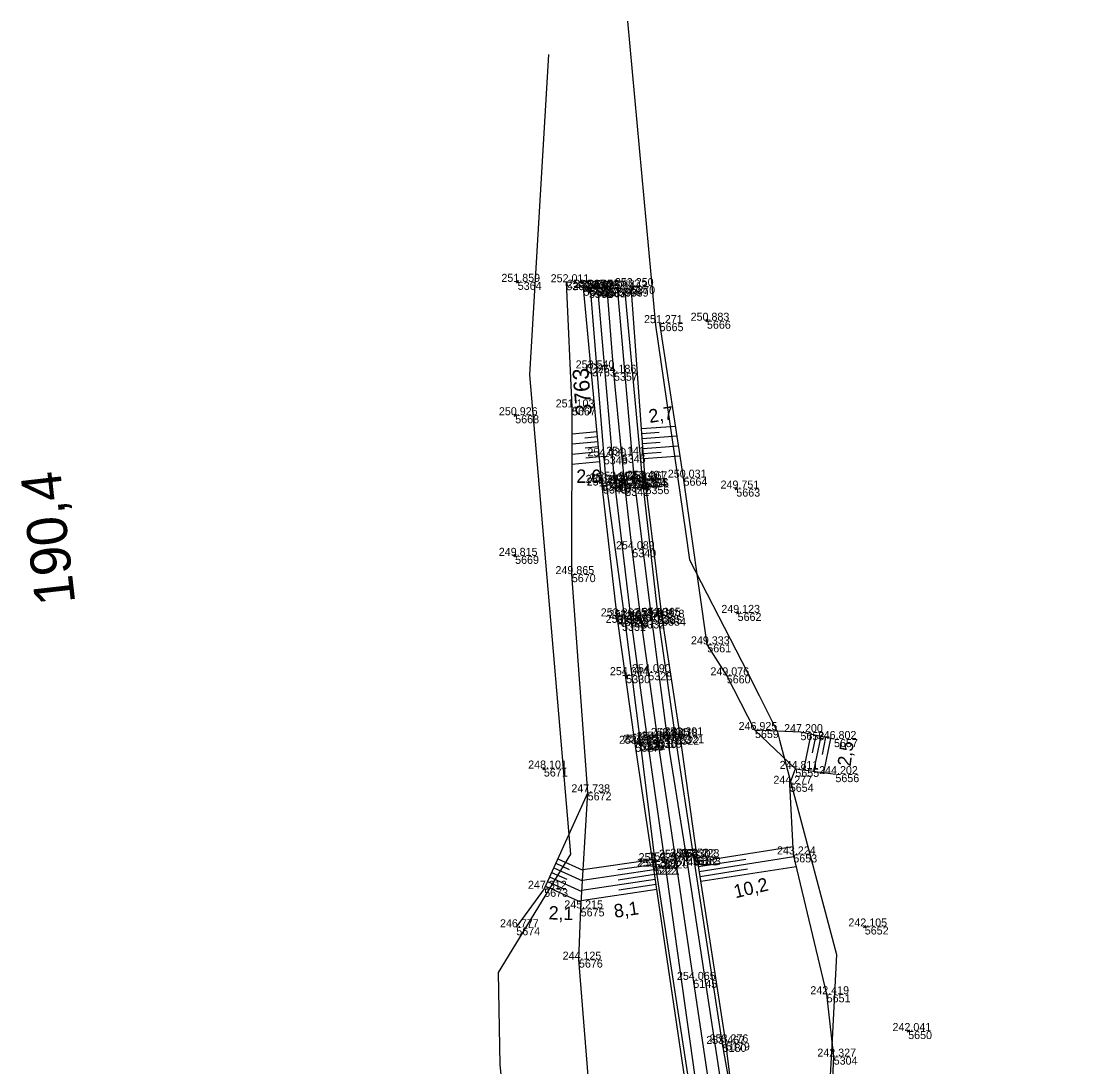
# Model space of a CAD drawing. Extents: x -809970 to -809480, y -1011362 to -1010672.
# Drawn here: x -809970 to -809810.9, y -1010828.7 to -1010672 of the extents above; entities that cross this region are included whole.
import ezdxf

# ---------------------------------------------------------------- set-up
doc = ezdxf.new("R2010")
doc.units = 0
for name, color, linetype in [('Vrstva 1', 7, 'Continuous'), ('Vrstva 4', 7, 'Continuous'), ('Vrstva 48', 7, 'Continuous'), ('Vrstva 49', 7, 'Continuous'), ('Vrstva 53', 7, 'Continuous'), ('Vrstva 60', 7, 'Continuous'), ('Vrstva 61', 7, 'Continuous'), ('Vrstva 63', 7, 'Continuous'), ('Vrstva 7', 7, 'Continuous')]:
    doc.layers.add(name, color=color, linetype=linetype)

msp = doc.modelspace()

# ---------------------------------------------------------------- linework, layer by layer
at = {"layer": 'Vrstva 1'}
msp.add_lwpolyline([(-809865.82, -1010838.83), (-809869.27, -1010815.69), (-809871.97, -1010797.4), (-809874.59, -1010779.68), (-809876.02, -1010769.59), (-809877.07, -1010761.83), (-809878.42, -1010751.16), (-809879.47, -1010741.97), (-809879.54, -1010741.3), (-809879.99, -1010737.01), (-809881.17, -1010724.71), (-809882.19, -1010712.11)], dxfattribs=at)
at = {"layer": 'Vrstva 4'}
for points in [[(-809867.76, -1010839.12), (-809868.41, -1010839.2), (-809868.55, -1010838.89), (-809868.98, -1010838.22), (-809869.98, -1010830.46), (-809874.92, -1010798.71), (-809877.19, -1010780.09), (-809879.53, -1010761.48), (-809882.36, -1010740.99), (-809884.68, -1010711.99)], [(-809821.49, -1011039.16), (-809826.21, -1011028.82), (-809833, -1011011.48), (-809837.78, -1010997.54), (-809838.81, -1010997.21), (-809843.28, -1010980.93), (-809843.04, -1010980.21), (-809846.29, -1010966.66), (-809849.29, -1010953.14), (-809852.71, -1010936.05), (-809854.79, -1010922.51), (-809857.87, -1010903.01), (-809861.56, -1010877.87), (-809862.28, -1010876.01), (-809867.76, -1010839.12), (-809867.78, -1010837.68), (-809868.98, -1010830.23), (-809873.56, -1010797.79), (-809876.12, -1010779.99), (-809878.6, -1010761.67), (-809881.09, -1010740.74), (-809883.61, -1010712.06)], [(-809864.68, -1010833.8), (-809870.28, -1010797.22), (-809873.18, -1010779.14), (-809875.56, -1010761.17), (-809878.1, -1010740.87), (-809880.65, -1010711.96)], [(-809863.76, -1010838.59), (-809863.3, -1010838.44), (-809863.34, -1010838.02), (-809863.28, -1010838.07), (-809862.82, -1010837.88), (-809863.19, -1010834.77), (-809864.88, -1010825.29), (-809869.18, -1010797.35), (-809871.95, -1010779.25), (-809874.53, -1010761.14), (-809876.89, -1010740.6), (-809879.55, -1010712.09)]]:
    msp.add_lwpolyline(points, dxfattribs=at)
at = {"layer": 'Vrstva 48'}
for p, q in [((-809883.7, -1010733.57), (-809887.46, -1010733.93)), ((-809877.06, -1010733.07), (-809871.94, -1010732.7)), ((-809877, -1010733.82), (-809874.41, -1010733.63)), ((-809883.56, -1010735.07), (-809887.46, -1010735.43)), ((-809883.63, -1010734.32), (-809885.54, -1010734.5)), ((-809876.95, -1010734.57), (-809871.71, -1010734.19)), ((-809876.9, -1010735.31), (-809874.24, -1010735.12)), ((-809876.84, -1010736.06), (-809871.48, -1010735.68)), ((-809883.42, -1010736.56), (-809887.46, -1010736.94)), ((-809883.49, -1010735.81), (-809885.47, -1010736)), ((-809883.34, -1010737.31), (-809885.41, -1010737.5)), ((-809876.79, -1010736.81), (-809874.08, -1010736.62)), ((-809876.74, -1010737.56), (-809871.25, -1010737.17)), ((-809883.27, -1010738.05), (-809887.47, -1010738.45)), ((-809851.65, -1010778.89), (-809852.75, -1010784.23)), ((-809850.91, -1010779.04), (-809851.46, -1010781.69)), ((-809850.18, -1010779.19), (-809851.26, -1010784.43)), ((-809849.44, -1010779.34), (-809849.98, -1010781.94)), ((-809848.71, -1010779.5), (-809849.77, -1010784.62)), ((-809868.62, -1010797.95), (-809854.34, -1010795.72)), ((-809889.59, -1010797.54), (-809885.82, -1010799.24)), ((-809875.42, -1010797.7), (-809885.82, -1010799.22)), ((-809868.5, -1010798.69), (-809861.4, -1010797.58)), ((-809868.38, -1010799.43), (-809854.2, -1010797.21)), ((-809890.21, -1010798.91), (-809885.91, -1010800.84)), ((-809889.9, -1010798.22), (-809887.88, -1010799.13)), ((-809875.2, -1010799.18), (-809885.91, -1010800.78)), ((-809875.31, -1010798.44), (-809880.59, -1010799.21)), ((-809868.27, -1010800.18), (-809861.15, -1010799.06)), ((-809868.15, -1010800.92), (-809853.85, -1010798.68)), ((-809891.14, -1010800.96), (-809888.6, -1010802.1)), ((-809890.83, -1010800.27), (-809886.01, -1010802.45)), ((-809890.52, -1010799.59), (-809888.24, -1010800.62)), ((-809874.98, -1010800.67), (-809886, -1010802.31)), ((-809875.09, -1010799.92), (-809880.52, -1010800.73)), ((-809891.45, -1010801.64), (-809886.11, -1010804.05)), ((-809874.76, -1010802.15), (-809886.09, -1010803.84)), ((-809874.87, -1010801.41), (-809880.46, -1010802.24))]:
    msp.add_line(p, q, dxfattribs=at)
at = {"layer": 'Vrstva 49'}
for p, q in [((-809895.77, -1010710.91), (-809895.42, -1010711.27)), ((-809895.77, -1010711.27), (-809895.42, -1010710.91)), ((-809867.4, -1010716.74), (-809867.05, -1010717.09)), ((-809867.4, -1010717.09), (-809867.05, -1010716.74)), ((-809896.14, -1010730.9), (-809895.79, -1010731.25)), ((-809896.14, -1010731.25), (-809895.79, -1010730.9)), ((-809863.01, -1010741.9), (-809862.65, -1010742.25)), ((-809863.01, -1010742.25), (-809862.65, -1010741.9)), ((-809896.16, -1010751.97), (-809895.81, -1010752.32)), ((-809896.16, -1010752.32), (-809895.81, -1010751.97)), ((-809862.81, -1010760.52), (-809862.46, -1010760.88)), ((-809862.81, -1010760.88), (-809862.46, -1010760.52)), ((-809891.85, -1010783.85), (-809891.5, -1010784.2)), ((-809891.85, -1010784.2), (-809891.5, -1010783.85)), ((-809843.75, -1010807.52), (-809843.39, -1010807.87)), ((-809843.75, -1010807.87), (-809843.39, -1010807.52)), ((-809837.23, -1010823.18), (-809836.88, -1010823.53)), ((-809837.23, -1010823.53), (-809836.88, -1010823.18))]:
    msp.add_line(p, q, dxfattribs=at)
for points in [[(-809868.41, -1010839.2), (-809879.86, -1010838.83), (-809879.84, -1010839.14), (-809878.72, -1010839.38), (-809879.75, -1010840.07), (-809884.6, -1010835.64), (-809886.42, -1010812.66), (-809886.16, -1010804.98), (-809885.11, -1010787.59), (-809887.49, -1010754.89), (-809887.46, -1010729.91), (-809888.3, -1010711.15)], [(-809863.11, -1010838.52), (-809862.82, -1010837.88), (-809863.19, -1010834.77), (-809864.38, -1010825.06), (-809868.72, -1010797.29), (-809871.24, -1010779.05), (-809873.96, -1010761.41), (-809876.51, -1010740.69), (-809878.58, -1010711.73)], [(-809868.41, -1010839.2), (-809868.55, -1010838.89), (-809869.28, -1010838.04), (-809870.54, -1010830.45), (-809875.27, -1010798.73), (-809877.97, -1010780.31), (-809880.7, -1010761.22), (-809882.97, -1010741.21), (-809885.74, -1010711.98)], [(-809853.98, -1010784.08), (-809860.03, -1010778.25), (-809864.26, -1010770.06), (-809867.18, -1010765.41), (-809870.74, -1010740.44), (-809874.32, -1010717.28)], [(-809848.18, -1010779.6), (-809853.21, -1010778.57), (-809860.03, -1010778.25)], [(-809863.11, -1010838.52), (-809851.66, -1010834.05), (-809851.44, -1010834.43), (-809852.35, -1010834.88), (-809850.69, -1010835.64), (-809848.92, -1010834.16), (-809848.4, -1010831.5), (-809848.23, -1010827.19), (-809849.28, -1010817.84), (-809854.28, -1010796.89), (-809854.81, -1010786.31), (-809853.98, -1010784.08), (-809847.97, -1010784.86)], [(-809885.11, -1010787.59), (-809891.63, -1010802.04), (-809895.81, -1010807.81)]]:
    msp.add_lwpolyline(points, dxfattribs=at)
at = {"layer": 'Vrstva 53'}
for points in [[(-809879.15, -1010672.04), (-809874.93, -1010717.6), (-809870.46, -1010748.48), (-809869.85, -1010752.77), (-809861.14, -1010769.64), (-809859.41, -1010773.1), (-809856.66, -1010778.59), (-809856.35, -1010779.75), (-809854.75, -1010785.76), (-809847.8, -1010811.91), (-809848.47, -1010824.63), (-809848.99, -1010834.52)], [(-809810.89, -1011076.81), (-809836.26, -1011028.53), (-809850.32, -1011003.33), (-809854.51, -1011000.24), (-809856.34, -1010998.68), (-809859.52, -1010995.97), (-809864.77, -1010992.44), (-809865.72, -1010986.44), (-809870.58, -1010955.65), (-809883.99, -1010901.78), (-809890.33, -1010872.36), (-809892.39, -1010868.68), (-809893.92, -1010865.41), (-809894.78, -1010861.65), (-809898.21, -1010828.41), (-809898.47, -1010814.6), (-809887.66, -1010796.86), (-809893.8, -1010725.05), (-809890.92, -1010677.02)]]:
    msp.add_lwpolyline(points, dxfattribs=at)
at = {"layer": 'Vrstva 60'}
for p, q in [((-809895.6, -1010711.09), (-809895.6, -1010711.09)), ((-809888.3, -1010711.15), (-809888.3, -1010711.15)), ((-809878.58, -1010711.73), (-809878.58, -1010711.73)), ((-809885.74, -1010711.98), (-809885.74, -1010711.98)), ((-809884.92, -1010712.31), (-809884.92, -1010712.31)), ((-809884.68, -1010711.99), (-809884.68, -1010711.99)), ((-809883.61, -1010712.06), (-809883.61, -1010712.06)), ((-809882.92, -1010712.22), (-809882.92, -1010712.22)), ((-809882.19, -1010712.11), (-809882.19, -1010712.11)), ((-809880.65, -1010711.96), (-809880.65, -1010711.96)), ((-809879.55, -1010712.09), (-809879.55, -1010712.09)), ((-809874.32, -1010717.28), (-809874.32, -1010717.28)), ((-809867.23, -1010716.92), (-809867.23, -1010716.92)), ((-809884.46, -1010724.06), (-809884.46, -1010724.06)), ((-809881.17, -1010724.71), (-809881.17, -1010724.71)), ((-809887.46, -1010729.91), (-809887.46, -1010729.91)), ((-809895.97, -1010731.08), (-809895.97, -1010731.08)), ((-809882.7, -1010737.23), (-809882.7, -1010737.23)), ((-809879.99, -1010737.01), (-809879.99, -1010737.01)), ((-809870.74, -1010740.44), (-809870.74, -1010740.44)), ((-809882.97, -1010741.21), (-809882.97, -1010741.21)), ((-809882.81, -1010741.61), (-809882.81, -1010741.61)), ((-809882.36, -1010740.99), (-809882.36, -1010740.99)), ((-809881.09, -1010740.74), (-809881.09, -1010740.74)), ((-809879.54, -1010741.3), (-809879.54, -1010741.3)), ((-809879.47, -1010741.97), (-809879.47, -1010741.97)), ((-809878.1, -1010740.87), (-809878.1, -1010740.87)), ((-809876.89, -1010740.6), (-809876.89, -1010740.6)), ((-809876.51, -1010740.69), (-809876.51, -1010740.69)), ((-809876.44, -1010741.7), (-809876.44, -1010741.7)), ((-809862.83, -1010742.07), (-809862.83, -1010742.07)), ((-809878.42, -1010751.16), (-809878.42, -1010751.16)), ((-809895.99, -1010752.15), (-809895.99, -1010752.15)), ((-809887.49, -1010754.89), (-809887.49, -1010754.89)), ((-809875.56, -1010761.17), (-809875.56, -1010761.17)), ((-809874.53, -1010761.14), (-809874.53, -1010761.14)), ((-809862.63, -1010760.7), (-809862.63, -1010760.7)), ((-809880.7, -1010761.22), (-809880.7, -1010761.22)), ((-809879.96, -1010762.19), (-809879.96, -1010762.19)), ((-809879.53, -1010761.48), (-809879.53, -1010761.48)), ((-809878.6, -1010761.67), (-809878.6, -1010761.67)), ((-809877.07, -1010761.83), (-809877.07, -1010761.83)), ((-809873.96, -1010761.41), (-809873.96, -1010761.41)), ((-809867.18, -1010765.41), (-809867.18, -1010765.41)), ((-809879.33, -1010770.03), (-809879.33, -1010770.03)), ((-809876.02, -1010769.59), (-809876.02, -1010769.59)), ((-809864.26, -1010770.06), (-809864.26, -1010770.06)), ((-809860.03, -1010778.25), (-809860.03, -1010778.25)), ((-809853.21, -1010778.57), (-809853.21, -1010778.57)), ((-809877.37, -1010780.14), (-809877.37, -1010780.14)), ((-809877.19, -1010780.09), (-809877.19, -1010780.09)), ((-809876.12, -1010779.99), (-809876.12, -1010779.99)), ((-809875.34, -1010779.76), (-809875.34, -1010779.76)), ((-809874.59, -1010779.68), (-809874.59, -1010779.68)), ((-809873.18, -1010779.14), (-809873.18, -1010779.14)), ((-809871.95, -1010779.25), (-809871.95, -1010779.25)), ((-809871.24, -1010779.05), (-809871.24, -1010779.05)), ((-809848.18, -1010779.6), (-809848.18, -1010779.6)), ((-809877.97, -1010780.31), (-809877.97, -1010780.31)), ((-809891.68, -1010784.02), (-809891.68, -1010784.02)), ((-809853.98, -1010784.08), (-809853.98, -1010784.08)), ((-809847.97, -1010784.86), (-809847.97, -1010784.86)), ((-809854.81, -1010786.31), (-809854.81, -1010786.31)), ((-809885.11, -1010787.59), (-809885.11, -1010787.59)), ((-809871.97, -1010797.4), (-809871.97, -1010797.4)), ((-809870.28, -1010797.22), (-809870.28, -1010797.22)), ((-809869.18, -1010797.35), (-809869.18, -1010797.35)), ((-809868.72, -1010797.29), (-809868.72, -1010797.29)), ((-809854.28, -1010796.89), (-809854.28, -1010796.89)), ((-809875.27, -1010798.73), (-809875.27, -1010798.73)), ((-809875.03, -1010797.9), (-809875.03, -1010797.9)), ((-809874.92, -1010798.71), (-809874.92, -1010798.71)), ((-809873.56, -1010797.79), (-809873.56, -1010797.79)), ((-809891.63, -1010802.04), (-809891.63, -1010802.04)), ((-809886.16, -1010804.98), (-809886.16, -1010804.98)), ((-809895.81, -1010807.81), (-809895.81, -1010807.81)), ((-809843.57, -1010807.69), (-809843.57, -1010807.69)), ((-809886.42, -1010812.66), (-809886.42, -1010812.66)), ((-809869.27, -1010815.69), (-809869.27, -1010815.69)), ((-809849.28, -1010817.84), (-809849.28, -1010817.84)), ((-809837.06, -1010823.36), (-809837.06, -1010823.36)), ((-809864.88, -1010825.29), (-809864.88, -1010825.29)), ((-809864.38, -1010825.06), (-809864.38, -1010825.06)), ((-809848.23, -1010827.19), (-809848.23, -1010827.19))]:
    msp.add_line(p, q, dxfattribs=at)
at = {"layer": 'Vrstva 63'}
msp.add_line((-809884.46, -1010724.11), (-809884.47, -1010724.01), dxfattribs=at)
msp.add_circle((-809884.46, -1010724.06), 0.756, dxfattribs=at)
at = {"layer": 'Vrstva 7'}
for p, q in [((-809884.89, -1010712.81), (-809884.96, -1010711.81)), ((-809885.42, -1010712.35), (-809884.43, -1010712.28)), ((-809883.2, -1010737.28), (-809882.2, -1010737.19)), ((-809882.65, -1010737.73), (-809882.75, -1010736.74)), ((-809883.31, -1010741.67), (-809882.31, -1010741.56)), ((-809882.76, -1010742.11), (-809882.86, -1010741.12)), ((-809876.45, -1010741.65), (-809876.43, -1010741.75)), ((-809880.45, -1010762.25), (-809879.46, -1010762.13)), ((-809879.89, -1010762.69), (-809880.02, -1010761.7)), ((-809879.83, -1010770.1), (-809878.84, -1010769.96)), ((-809879.26, -1010770.53), (-809879.4, -1010769.53)), ((-809877.87, -1010780.21), (-809876.88, -1010780.07)), ((-809877.3, -1010780.64), (-809877.44, -1010779.65)), ((-809874.96, -1010798.4), (-809875.11, -1010797.41)), ((-809875.53, -1010797.97), (-809874.54, -1010797.83))]:
    msp.add_line(p, q, dxfattribs=at)
for centre, radius in [((-809879.46, -1010742.05), 0.75), ((-809876.44, -1010741.7), 0.5)]:
    msp.add_circle(centre, radius, dxfattribs=at)

# ---------------------------------------------------------------- texts
at = {"layer": 'Vrstva 48'}
for s, rotation, p in [('2,7', 8.7757, (-809875.81, -1010732.24)), ('2,6', 359.9243, (-809886.82, -1010741.21)), ('2,5', 82.5584, (-809845.7, -1010783.76)), ('10,2', 13.4222, (-809862.95, -1010803.47)), ('8,1', 8.4755, (-809881.03, -1010806.4)), ('2,1', 358.1117, (-809890.99, -1010806.62))]:
    msp.add_text(s, height=2, rotation=rotation, dxfattribs=at).set_placement(p)
at = {"layer": 'Vrstva 60'}
for s, p in [('5364', (-809895.6, -1010712.29)), ('5363', (-809888.3, -1010712.34)), ('5370', (-809878.58, -1010712.93)), ('5365', (-809885.74, -1010713.18)), ('5362', (-809884.92, -1010713.51)), ('5366', (-809884.68, -1010713.19)), ('5367', (-809883.61, -1010713.26)), ('5361', (-809882.92, -1010713.42)), ('5359', (-809882.19, -1010713.31)), ('5368', (-809880.65, -1010713.16)), ('5369', (-809879.55, -1010713.3)), ('5665', (-809874.32, -1010718.48)), ('5666', (-809867.23, -1010718.12)), ('3763', (-809884.46, -1010725.26)), ('5357', (-809881.17, -1010725.91)), ('5667', (-809887.46, -1010731.11)), ('5668', (-809895.97, -1010732.28)), ('5348', (-809882.7, -1010738.43)), ('5346', (-809879.99, -1010738.21)), ('5664', (-809870.74, -1010741.64)), ('5350', (-809882.97, -1010742.41)), ('5349', (-809882.81, -1010742.82)), ('5351', (-809882.36, -1010742.19)), ('5352', (-809881.09, -1010741.94)), ('5344', (-809879.54, -1010742.5)), ('5342', (-809879.47, -1010743.17)), ('5353', (-809878.1, -1010742.07)), ('5354', (-809876.89, -1010741.8)), ('5355', (-809876.51, -1010741.89)), ('5356', (-809876.44, -1010742.9)), ('5663', (-809862.83, -1010743.27)), ('5340', (-809878.42, -1010752.36)), ('5669', (-809895.99, -1010753.35)), ('5670', (-809887.49, -1010756.09)), ('5336', (-809875.56, -1010762.37)), ('5335', (-809874.53, -1010762.34)), ('5662', (-809862.63, -1010761.9)), ('5339', (-809880.7, -1010762.42)), ('5331', (-809879.96, -1010763.39)), ('5338', (-809879.53, -1010762.68)), ('5337', (-809878.6, -1010762.87)), ('5332', (-809877.07, -1010763.03)), ('5334', (-809873.96, -1010762.61)), ('5661', (-809867.18, -1010766.61)), ('5330', (-809879.33, -1010771.23)), ('5328', (-809876.02, -1010770.79)), ('5660', (-809864.26, -1010771.26)), ('5659', (-809860.03, -1010779.45)), ('5658', (-809853.21, -1010779.77)), ('5326', (-809877.37, -1010781.34)), ('5325', (-809877.19, -1010781.29)), ('5324', (-809876.12, -1010781.19)), ('5320', (-809875.34, -1010780.96)), ('5318', (-809874.59, -1010780.88)), ('5323', (-809873.18, -1010780.34)), ('5322', (-809871.95, -1010780.45)), ('5321', (-809871.24, -1010780.25)), ('5657', (-809848.18, -1010780.81)), ('5327', (-809877.97, -1010781.51)), ('5671', (-809891.68, -1010785.22)), ('5655', (-809853.98, -1010785.28)), ('5656', (-809847.97, -1010786.06)), ('5654', (-809854.81, -1010787.51)), ('5672', (-809885.11, -1010788.79)), ('5220', (-809873.56, -1010798.99)), ('5147', (-809871.97, -1010798.6)), ('5181', (-809870.28, -1010798.42)), ('5182', (-809869.18, -1010798.55)), ('5183', (-809868.72, -1010798.48)), ('5653', (-809854.28, -1010798.09)), ('5222', (-809875.27, -1010799.93)), ('5223', (-809875.03, -1010799.1)), ('5221', (-809874.92, -1010799.91)), ('5673', (-809891.63, -1010803.24)), ('5675', (-809886.16, -1010806.18)), ('5674', (-809895.81, -1010809.01)), ('5652', (-809843.57, -1010808.89)), ('5676', (-809886.42, -1010813.85)), ('5145', (-809869.27, -1010816.89)), ('5651', (-809849.28, -1010819.05)), ('5650', (-809837.06, -1010824.56)), ('5180', (-809864.88, -1010826.48)), ('5179', (-809864.38, -1010826.26)), ('5304', (-809848.23, -1010828.39))]:
    msp.add_text(s, height=1.2, dxfattribs=at).set_placement(p)
at = {"layer": 'Vrstva 61'}
for s, p in [('251.859', (-809898.05, -1010711.09)), ('252.011', (-809890.66, -1010711.15)), ('253.327', (-809888.19, -1010711.98)), ('254.070', (-809887.37, -1010712.31)), ('253.540', (-809887.13, -1010711.99)), ('254.085', (-809886.06, -1010712.06)), ('254.252', (-809885.37, -1010712.22)), ('254.211', (-809884.55, -1010712.11)), ('253.992', (-809883.09, -1010711.96)), ('253.442', (-809882, -1010712.09)), ('253.250', (-809881.03, -1010711.73)), ('251.271', (-809876.67, -1010717.28)), ('250.883', (-809869.68, -1010716.92)), ('253.540', (-809886.91, -1010724.06)), ('254.186', (-809883.62, -1010724.71)), ('251.103', (-809889.91, -1010729.91)), ('250.926', (-809898.42, -1010731.08)), ('254.030', (-809885.15, -1010737.23)), ('254.141', (-809882.34, -1010737.01)), ('253.272', (-809885.42, -1010741.21)), ('254.117', (-809885.26, -1010741.61)), ('253.404', (-809884.81, -1010740.99)), ('253.974', (-809883.54, -1010740.74)), ('254.133', (-809881.99, -1010741.3)), ('253.909', (-809880.56, -1010740.87)), ('253.401', (-809879.25, -1010740.6)), ('253.267', (-809878.97, -1010740.69)), ('253.805', (-809878.9, -1010741.7)), ('250.031', (-809873.1, -1010740.44)), ('254.131', (-809881.82, -1010741.97)), ('249.751', (-809865.19, -1010742.07)), ('254.089', (-809880.87, -1010751.16)), ('249.815', (-809898.44, -1010752.15)), ('249.865', (-809889.94, -1010754.89)), ('249.123', (-809865.08, -1010760.7)), ('253.262', (-809883.15, -1010761.22)), ('253.960', (-809882.41, -1010762.19)), ('253.463', (-809881.99, -1010761.48)), ('253.877', (-809881.05, -1010761.67)), ('254.070', (-809879.52, -1010761.83)), ('253.884', (-809878.01, -1010761.17)), ('253.365', (-809876.98, -1010761.14)), ('253.278', (-809876.41, -1010761.41)), ('249.333', (-809869.63, -1010765.41)), ('254.044', (-809881.78, -1010770.03)), ('254.090', (-809878.47, -1010769.59)), ('249.076', (-809866.71, -1010770.06)), ('246.925', (-809862.49, -1010778.25)), ('254.104', (-809877.79, -1010779.76)), ('254.086', (-809877.04, -1010779.68)), ('253.885', (-809875.64, -1010779.14)), ('253.418', (-809874.4, -1010779.25)), ('253.301', (-809873.6, -1010779.05)), ('247.200', (-809855.66, -1010778.57)), ('246.802', (-809850.63, -1010779.6)), ('253.133', (-809880.42, -1010780.31)), ('253.972', (-809879.82, -1010780.14)), ('253.304', (-809879.64, -1010780.09)), ('253.889', (-809878.57, -1010779.99)), ('248.101', (-809894.03, -1010784.02)), ('244.811', (-809856.33, -1010784.08)), ('244.202', (-809850.41, -1010784.86)), ('247.738', (-809887.56, -1010787.59)), ('244.277', (-809857.27, -1010786.31)), ('254.069', (-809874.43, -1010797.4)), ('253.853', (-809872.73, -1010797.22)), ('253.302', (-809871.62, -1010797.35)), ('253.223', (-809871.17, -1010797.29)), ('243.224', (-809856.73, -1010796.89)), ('253.219', (-809877.72, -1010798.73)), ('253.922', (-809877.48, -1010797.9)), ('253.377', (-809877.37, -1010798.71)), ('253.902', (-809876.01, -1010797.79)), ('247.312', (-809894.07, -1010802.04)), ('245.215', (-809888.62, -1010804.98)), ('246.777', (-809898.26, -1010807.81)), ('242.105', (-809846.03, -1010807.69)), ('244.125', (-809888.87, -1010812.66)), ('254.065', (-809871.73, -1010815.69)), ('242.419', (-809851.73, -1010817.84)), ('242.041', (-809839.41, -1010823.36)), ('253.467', (-809867.33, -1010825.29)), ('253.276', (-809866.83, -1010825.06)), ('242.327', (-809850.68, -1010827.19))]:
    msp.add_text(s, height=1.2, dxfattribs=at).set_placement(p)
at = {"layer": 'Vrstva 63'}
msp.add_text('3763', height=2.4, rotation=94.6518, dxfattribs=at).set_placement((-809884.46, -1010731.05))
at = {"layer": 'Vrstva 7'}
msp.add_text('190,4', height=6, rotation=96.4948, dxfattribs=at).set_placement((-809961.92, -1010759.2))

doc.saveas('drawing.dxf')
